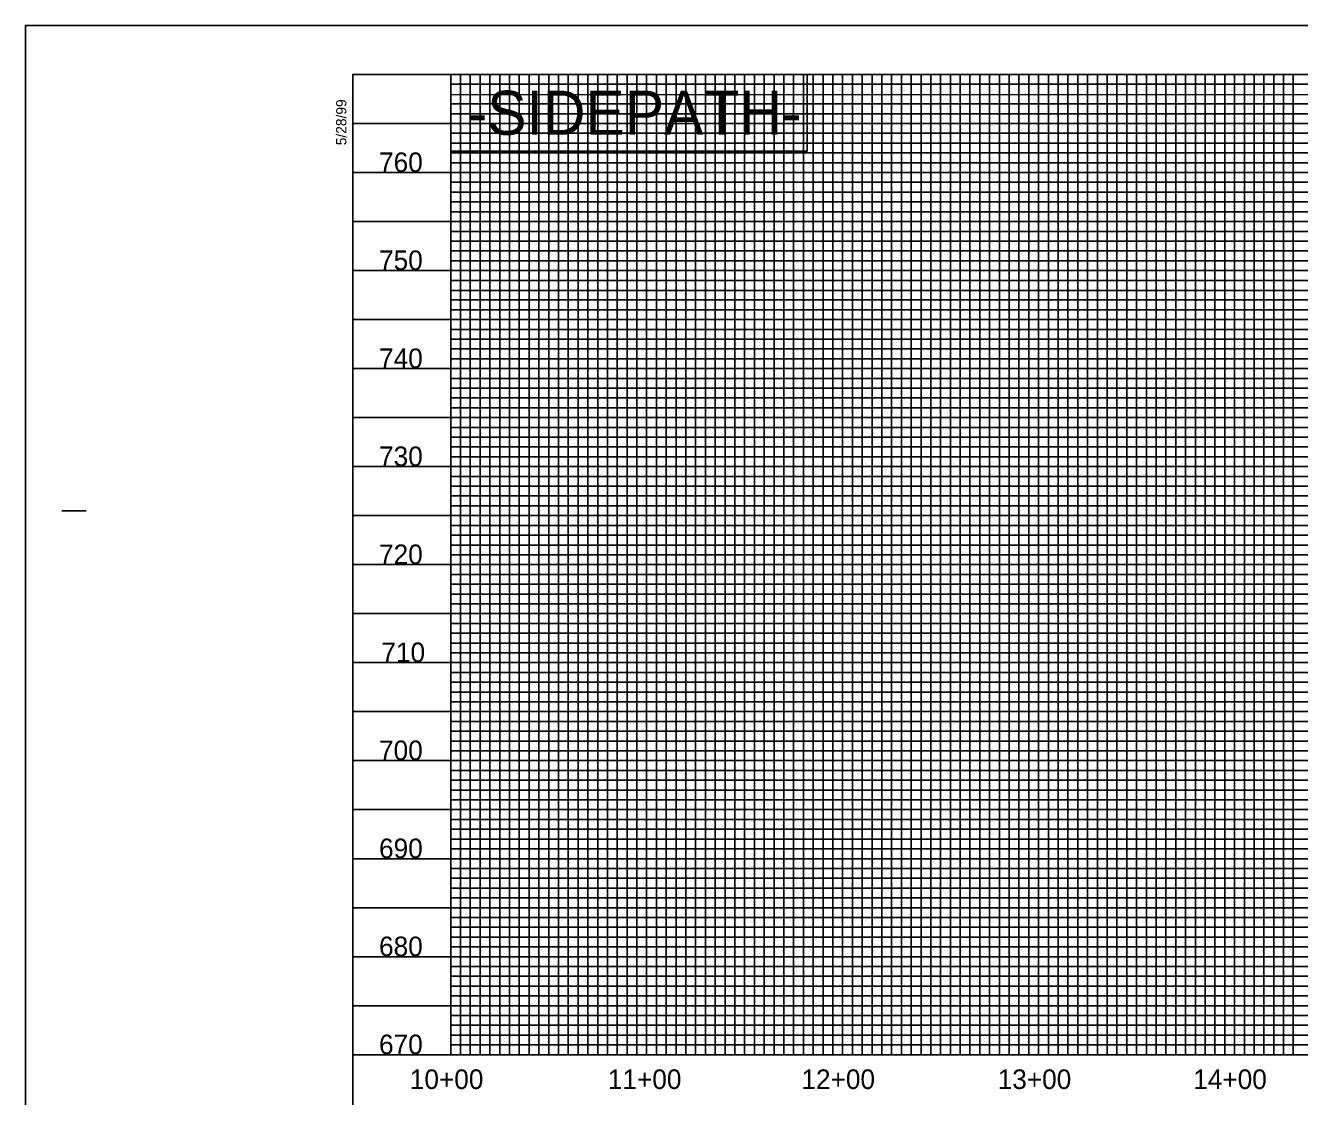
# Model space of a CAD drawing. Extents: x 1524869 to 1526553, y 501099 to 502199.
# Drawn here: x 1524869 to 1525519, y 501652 to 502199 of the extents above; entities that cross this region are included whole.
import ezdxf

# ---------------------------------------------------------------- set-up
doc = ezdxf.new("R2010")
doc.units = 0
for name, color, linetype in [('Exist Vertical Profile Horizontal Axis Label Major', 7, 'Continuous'), ('Exist Vertical Profile Vertical Axis Label', 7, 'Continuous'), ('Prop Grid Mask', 7, 'Continuous'), ('Prop Horizontal Alignment Curve and Spiral Data', 7, 'Continuous'), ('Sheet Layout Profile Border Port 1', 7, 'Continuous'), ('Sheet Plot Border Outside CELL', 7, 'Continuous'), ('Sheet Profile CELL', 7, 'Continuous'), ('Sheet Profile Grid Major CELL', 7, 'Continuous'), ('Sheet Profile Grid Middle CELL', 7, 'Continuous'), ('Sheet Profile Grid Minor CELL', 7, 'Continuous')]:
    doc.layers.add(name, color=color, linetype=linetype)

msp = doc.modelspace()

# ---------------------------------------------------------------- linework, layer by layer
at = {"layer": 'Prop Grid Mask'}
msp.add_lwpolyline([(1525086.08, 502134.52), (1525267.99, 502134.52), (1525267.99, 502173.56), (1525086.08, 502173.56)], close=True, dxfattribs=at)
at = {"layer": 'Sheet Layout Profile Border Port 1'}
msp.add_lwpolyline([(1525086.08, 502173.56), (1525086.08, 501673.56), (1526486.08, 501673.56), (1526486.08, 502012.51), (1526336.03, 502012.51), (1526336.08, 502173.56)], close=True, dxfattribs=at)
at = {"layer": 'Sheet Plot Border Outside CELL'}
msp.add_lwpolyline([(1524869.08, 501098.56), (1526553.08, 501098.56), (1526553.08, 502198.56), (1524869.08, 502198.56)], close=True, dxfattribs=at)
at = {"layer": 'Sheet Profile CELL'}
for p, q in [((1524887.58, 501951.06), (1524900.08, 501951.06)), ((1525036.08, 501673.56), (1526536.08, 501673.56))]:
    msp.add_line(p, q, dxfattribs=at)
msp.add_lwpolyline([(1526536.08, 502173.56), (1525036.08, 502173.56), (1525036.08, 501123.56), (1526536.08, 501123.56)], close=True, dxfattribs=at)
at = {"layer": 'Sheet Profile Grid Major CELL'}
for points in [[(1525086.08, 502173.56), (1525086.08, 501673.56), (1525136.08, 501673.56), (1525136.08, 502173.56), (1525186.08, 502173.56), (1525186.08, 501673.56), (1525236.08, 501673.56), (1525236.08, 502173.56), (1525286.08, 502173.56), (1525286.08, 501673.56), (1525336.08, 501673.56), (1525336.08, 502173.56), (1525386.08, 502173.56), (1525386.08, 501673.56), (1525436.08, 501673.56), (1525436.08, 502173.56), (1525486.08, 502173.56), (1525486.08, 501673.56), (1525536.08, 501673.56)], [(1525036.08, 502123.56), (1526336.08, 502123.56)], [(1526336.08, 502073.56), (1525036.08, 502073.56), (1525036.08, 502023.56), (1526336.08, 502023.56)], [(1526536.08, 501973.56), (1525036.08, 501973.56), (1525036.08, 501923.56), (1526536.08, 501923.56)], [(1526536.08, 501873.56), (1525036.08, 501873.56), (1525036.08, 501823.56), (1526536.08, 501823.56)], [(1526536.08, 501773.56), (1525036.08, 501773.56), (1525036.08, 501773.56), (1525036.08, 501723.56), (1526536.08, 501723.56)]]:
    msp.add_lwpolyline(points, dxfattribs=at)
at = {"layer": 'Sheet Profile Grid Middle CELL'}
msp.add_line((1525036.08, 502148.56), (1526336.03, 502148.56), dxfattribs=at)
for points in [[(1525111.08, 502173.56), (1525111.08, 501673.56), (1525161.08, 501673.56), (1525161.08, 502173.56), (1525211.08, 502173.56), (1525211.08, 501673.56), (1525261.08, 501673.56), (1525261.08, 502173.56), (1525311.08, 502173.56), (1525311.08, 501673.56), (1525361.08, 501673.56), (1525361.08, 502173.56), (1525411.08, 502173.56), (1525411.08, 501673.56), (1525461.08, 501673.56), (1525461.08, 502173.56), (1525511.08, 502173.56), (1525511.08, 501673.56), (1525561.08, 501673.56)], [(1526336.08, 502098.56), (1525036.08, 502098.56), (1525036.08, 502048.56), (1526336.08, 502048.56)], [(1526536.08, 501998.56), (1525036.08, 501998.56), (1525036.08, 501948.56), (1526361.08, 501948.56)], [(1526536.08, 501898.56), (1525036.08, 501898.56), (1525036.08, 501848.56), (1526536.08, 501848.56)], [(1526536.08, 501798.56), (1525036.08, 501798.56), (1525036.08, 501748.56), (1526536.08, 501748.56)], [(1526536.08, 501698.56), (1525036.08, 501698.56)]]:
    msp.add_lwpolyline(points, dxfattribs=at)
at = {"layer": 'Sheet Profile Grid Minor CELL'}
for p, q in [((1525086.08, 502168.56), (1526336.08, 502168.56)), ((1525086.08, 502163.56), (1525086.08, 502163.56)), ((1525086.08, 502163.56), (1525086.08, 502163.56)), ((1526336.08, 502163.56), (1525086.08, 502163.21)), ((1525086.08, 502158.56), (1526336.08, 502158.56)), ((1526336.03, 502038.56), (1525086.08, 502038.56)), ((1526336.08, 502033.56), (1525086.08, 502033.56)), ((1526336.08, 502028.56), (1525086.08, 502028.56)), ((1525086.08, 502018.56), (1526336.08, 502018.56)), ((1526336.08, 502013.56), (1525086.08, 502013.56)), ((1525086.08, 502008.56), (1526486.08, 502008.56)), ((1526486.08, 501988.56), (1525086.08, 501988.56)), ((1525086.08, 501983.56), (1526486.08, 501983.56)), ((1526486.08, 501963.56), (1525086.08, 501963.56)), ((1525086.08, 501958.56), (1526486.08, 501958.56)), ((1526486.08, 501938.56), (1525086.08, 501938.56)), ((1525086.08, 501933.56), (1526486.08, 501933.56)), ((1526486.08, 501928.56), (1525086.08, 501928.56)), ((1525086.08, 501918.56), (1526486.08, 501918.56)), ((1526486.08, 501913.56), (1525086.08, 501913.56)), ((1525086.08, 501908.56), (1526486.08, 501908.56)), ((1526486.08, 501903.56), (1525086.08, 501903.56)), ((1525086.08, 501893.56), (1526486.08, 501893.56)), ((1526486.08, 501888.56), (1525086.08, 501888.56)), ((1525086.08, 501883.56), (1526486.08, 501883.56)), ((1526486.08, 501878.56), (1525086.08, 501878.56)), ((1525086.08, 501868.56), (1526486.08, 501868.56)), ((1526486.08, 501863.56), (1525086.08, 501863.56)), ((1525086.08, 501858.56), (1526486.08, 501858.56)), ((1526486.08, 501853.56), (1525086.08, 501853.56)), ((1525086.08, 501843.56), (1526486.08, 501843.56)), ((1526486.08, 501838.56), (1525086.08, 501838.56)), ((1525086.08, 501833.56), (1526486.08, 501833.56)), ((1526486.08, 501828.56), (1525086.08, 501828.56)), ((1525086.08, 501818.56), (1526486.08, 501818.56)), ((1526486.08, 501813.56), (1525086.08, 501813.56)), ((1525086.08, 501808.56), (1526486.08, 501808.56)), ((1526486.08, 501803.56), (1525086.08, 501803.56)), ((1525086.08, 501793.56), (1526486.08, 501793.56)), ((1526486.08, 501788.56), (1525086.08, 501788.56)), ((1526486.08, 501783.56), (1525086.08, 501783.56)), ((1526486.08, 501778.56), (1525086.08, 501778.56)), ((1525086.08, 501768.56), (1526486.08, 501768.56)), ((1526486.08, 501763.56), (1525086.08, 501763.56)), ((1525086.08, 501758.56), (1526486.08, 501758.56)), ((1526486.08, 501753.56), (1525086.08, 501753.56)), ((1525086.08, 501743.56), (1526486.08, 501743.56)), ((1526486.08, 501738.56), (1525086.08, 501738.56)), ((1525086.08, 501733.56), (1526486.08, 501733.56)), ((1526486.08, 501728.56), (1525086.08, 501728.56)), ((1525086.08, 501718.56), (1526486.08, 501718.56)), ((1526486.08, 501713.56), (1525086.08, 501713.56)), ((1525086.08, 501708.56), (1526486.08, 501708.56)), ((1526486.08, 501703.56), (1525086.08, 501703.56)), ((1525086.08, 501693.56), (1526486.08, 501693.56)), ((1526486.08, 501688.56), (1525086.08, 501688.56)), ((1525086.08, 501683.56), (1526486.08, 501683.56))]:
    msp.add_line(p, q, dxfattribs=at)
for points in [[(1525091.08, 502173.56), (1525091.08, 501673.56), (1525096.08, 501673.56), (1525096.08, 502173.56), (1525101.08, 502173.56), (1525101.08, 501673.56), (1525106.08, 501673.56), (1525106.08, 502173.56), (1525116.08, 502173.56), (1525116.08, 501673.56), (1525121.08, 501673.56), (1525121.08, 502173.56), (1525126.08, 502173.56), (1525126.08, 501673.56), (1525131.08, 501673.56), (1525141.08, 501673.56), (1525146.08, 501673.56), (1525146.08, 502173.56), (1525151.08, 502173.56), (1525151.08, 501673.56), (1525156.08, 501673.56), (1525156.08, 502173.56), (1525166.08, 502173.56), (1525166.08, 501673.56), (1525171.08, 501673.56), (1525171.08, 502173.56), (1525176.08, 502173.56), (1525176.08, 501673.56), (1525181.08, 501673.56), (1525181.08, 502173.56), (1525191.08, 502173.56), (1525191.08, 501673.56), (1525196.08, 501673.56), (1525196.08, 502173.56), (1525201.08, 502173.56), (1525201.08, 501673.56), (1525206.08, 501673.56), (1525206.08, 502173.56), (1525216.08, 502173.56), (1525216.08, 501673.56), (1525221.08, 501673.56), (1525221.08, 502173.56), (1525226.08, 502173.56), (1525226.08, 501673.56), (1525231.08, 501673.56), (1525231.08, 502173.56), (1525241.08, 502173.56), (1525241.08, 501673.56), (1525246.08, 501673.56), (1525246.08, 502173.56), (1525251.08, 502173.56), (1525251.08, 501673.56), (1525256.08, 501673.56), (1525256.08, 502173.56), (1525266.08, 502173.56), (1525266.08, 501673.56), (1525271.08, 501673.56), (1525271.08, 502173.56), (1525276.08, 502173.56), (1525276.08, 501673.56), (1525281.08, 501673.56), (1525281.08, 502173.56), (1525291.08, 502173.56), (1525291.08, 501673.56), (1525296.08, 501673.56), (1525296.08, 502173.56), (1525301.08, 502173.56), (1525301.08, 501673.56)], [(1525131.08, 501673.56), (1525131.08, 502173.56), (1525141.08, 502173.56), (1525141.08, 501673.56)], [(1525301.08, 501673.56), (1525306.08, 501673.56), (1525306.08, 502173.56), (1525316.08, 502173.56), (1525316.08, 501673.56), (1525321.08, 501673.56), (1525321.08, 502173.56), (1525326.08, 502173.56), (1525326.08, 501673.56), (1525331.08, 501673.56), (1525331.08, 502173.56), (1525341.08, 502173.56), (1525341.08, 501673.56), (1525346.08, 501673.56), (1525346.08, 502173.56), (1525351.08, 502173.56), (1525351.08, 501673.56), (1525356.08, 501673.56), (1525356.08, 502173.56), (1525366.08, 502173.56), (1525366.08, 501673.56), (1525371.08, 501673.56), (1525371.08, 502173.56), (1525376.08, 502173.56), (1525376.08, 501673.56), (1525381.08, 501673.56), (1525381.08, 502173.56), (1525391.08, 502173.56), (1525391.08, 501673.56), (1525396.08, 501673.56), (1525396.08, 502173.56), (1525401.08, 502173.56), (1525401.08, 501673.56), (1525406.08, 501673.56), (1525406.08, 502173.56), (1525416.08, 502173.56), (1525416.08, 501673.56), (1525421.08, 501673.56), (1525421.08, 502173.56), (1525426.08, 502173.56), (1525426.08, 501673.56), (1525431.08, 501673.56), (1525431.08, 502173.56), (1525441.08, 502173.56), (1525441.08, 501673.56), (1525446.08, 501673.56), (1525446.08, 502173.56), (1525451.08, 502173.56), (1525451.08, 501673.56), (1525456.08, 501673.56), (1525456.08, 502173.56), (1525466.08, 502173.56), (1525466.08, 501673.56), (1525471.08, 501673.56), (1525471.08, 502173.56), (1525476.08, 502173.56), (1525476.08, 501673.56), (1525481.08, 501673.56), (1525481.08, 502173.56), (1525491.08, 502173.56), (1525491.08, 501673.56), (1525496.08, 501673.56), (1525496.08, 502173.56), (1525501.08, 502173.56), (1525501.08, 501673.56), (1525506.08, 501673.56), (1525506.08, 502173.56), (1525516.08, 502173.56), (1525516.08, 501673.56), (1525521.08, 501673.56)], [(1526336.08, 502153.56), (1525086.08, 502153.56), (1525086.08, 502143.56), (1526336.08, 502143.56)], [(1526336.03, 502138.56), (1525086.08, 502138.56), (1525086.08, 502133.56), (1526336.08, 502133.56)], [(1526336.08, 502128.56), (1525086.08, 502128.56), (1525086.08, 502118.56), (1526336.08, 502118.56)], [(1526336.08, 502113.56), (1525086.08, 502113.56), (1525086.08, 502108.56), (1526336.08, 502108.56)], [(1526336.08, 502103.56), (1525086.08, 502103.56), (1525086.08, 502093.56), (1526336.08, 502093.56)], [(1526336.08, 502088.56), (1525086.08, 502088.56), (1525086.08, 502083.56), (1526336.08, 502083.56)], [(1526336.08, 502078.56), (1525086.08, 502078.56), (1525086.08, 502068.56), (1526336.08, 502068.56)], [(1526336.08, 502063.46), (1525086.18, 502063.46), (1525086.18, 502058.56), (1526336.08, 502058.56)], [(1526336.08, 502053.56), (1525086.08, 502053.56), (1525086.08, 502043.56), (1526336.08, 502043.56)], [(1526486.08, 502003.56), (1525086.08, 502003.56), (1525086.08, 501993.56), (1526486.08, 501993.56)], [(1526486.08, 501978.56), (1525086.08, 501978.56), (1525086.08, 501968.56), (1526486.08, 501968.56)], [(1526486.08, 501953.56), (1525086.08, 501953.56), (1525086.08, 501943.56), (1526486.08, 501943.56)], [(1526486.08, 501678.56), (1525086.08, 501678.56)]]:
    msp.add_lwpolyline(points, dxfattribs=at)

# ---------------------------------------------------------------- texts
at = {"layer": 'Exist Vertical Profile Horizontal Axis Label Major'}
for s, p in [('10+00', (1525065.21, 501656.06)), ('11+00', (1525166.27, 501656.06)), ('12+00', (1525265.05, 501656.06)), ('13+00', (1525365.21, 501656.06)), ('14+00', (1525465, 501656.06))]:
    msp.add_text(s, height=10, dxfattribs=at).set_placement(p)
at = {"layer": 'Exist Vertical Profile Vertical Axis Label'}
for s, p in [('760', (1525049.51, 502123.81)), ('750', (1525049.51, 502073.81)), ('740', (1525049.51, 502023.81)), ('730', (1525049.51, 501973.81)), ('720', (1525049.51, 501923.81)), ('710', (1525050.71, 501873.81)), ('700', (1525049.51, 501823.81)), ('690', (1525049.51, 501773.81)), ('680', (1525049.51, 501723.81)), ('670', (1525049.51, 501673.81))]:
    msp.add_text(s, height=10, dxfattribs=at).set_placement(p)
at = {"layer": 'Prop Horizontal Alignment Curve and Spiral Data'}
msp.add_text('-SIDEPATH-', height=22.5, rotation=360, dxfattribs=at).set_placement((1525094.68, 502142.79))
at = {"layer": 'Sheet Profile CELL'}
msp.add_text('5/28/99', height=5.25, rotation=90, dxfattribs=at).set_placement((1525032.84, 502137.47))

doc.saveas('drawing.dxf')
